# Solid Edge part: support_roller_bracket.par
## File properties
Title: Support roller bracket
Author: Abhinav Rai
Template: Normal.par
Last saved by: Cadcim
Revision: 17
Application: Solid Edge
Material: aluminum
Density: 0 kg/mm^3
Accuracy: 0.99
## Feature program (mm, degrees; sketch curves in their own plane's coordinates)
sketch for "unnamed Protrusion 1" #1 plane through (0, 0, 0) normal (0, -1, 0) x-axis (1, 0, 0)
  circle centre (0, -138.9237) radius 3.81
sketch for "unnamed Protrusion 1" #2 plane through (0, 0, 0) normal (0, -1, 0) x-axis (1, 0, 0)
  line (143.637, -99.9249) -> (-143.637, -99.9249)
  line (-143.637, -99.9249) -> (-143.637, -115.1647)
  line (-143.637, -115.1647) -> (-61.0846, -156.7704)
  line (-61.0846, -156.7704) -> (-61.0846, -162.9363)
  line (-61.0846, -162.9363) -> (61.0846, -162.9363)
  line (61.0846, -156.7704) -> (61.0846, -162.9363)
  line (143.637, -115.1647) -> (61.0846, -156.7704)
  line (143.637, -99.9249) -> (143.637, -115.1647)
  dimension (linear) = 143.637
extrude "unnamed Protrusion 1" add finite 101.6 symmetric
fillet "Round_1" radius 31.75
fillet "Round_2" radius 6.35
sketch for "unnamed Protrusion 2" plane through (0, 0, 67.2512) normal (1, 0, 0) x-axis (0, 1, 0)
  arc centre (-23.4135, -61.792) radius 19.05 from (-23.4135, -42.742) to (-42.405, -60.3002) ccw
  line (-50.8, -167.1761) -> (-42.405, -60.3002)
  line (-50.8, -167.1761) -> (50.8, -167.1761)
  line (45.7777, -60.8928) -> (50.8, -167.1761)
  arc centre (26.749, -61.792) radius 19.05 from (26.749, -42.742) to (45.7777, -60.8928) cw
  line (19.05, -42.742) -> (26.749, -42.742)
  line (19.05, -64.967) -> (19.05, -42.742)
  arc centre (0, -64.967) radius 19.05 from (-19.05, -64.967) to (19.05, -64.967) ccw
  line (-19.05, -42.742) -> (-19.05, -64.967)
  line (-23.4135, -42.742) -> (-19.05, -42.742)
extrude "unnamed Protrusion 2" add to key point symmetric
sketch for "ExtrudedCutout_1" plane through (0, 0, 0) normal (0, -1, 0) x-axis (1, 0, 0)
  line (-128.3193, 24.5092) -> (125.6319, 24.5092)
  line (125.6319, 24.5092) -> (125.6319, -99.9249)
  line (125.6319, -99.9249) -> (-128.3193, -99.9249)
  line (-128.3193, -99.9249) -> (-128.3193, 24.5092)
extrude "ExtrudedCutout_1" cut finite 203.2 symmetric
chamfer "Chamfer_1" setback 5.08
rib "Rib_1"  Thickness = 25.4 mm
mirror "unnamed Mirror 1" of "Rib_1" about plane through (0, 0, 0) normal (1, 0, 0)
rib "unnamed Rib 1"
sketch for "Hole_1" plane through (0.1259, 0, -162.9363) normal (0, 0, -1) x-axis (-1, 0, 0)
  hole centre (0.1259, 0) bore radius 25.4
hole "Hole_1" diameter 50.8 through
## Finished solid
Body 1: solid body, 55 faces, 142 edges, 86 vertices.
  Faces by surface: plane 38, cylinder 17
  Edges by curve: line 106, circle 34, intersection 2
Bounding box of the edges (mm): 379.121 x 101.600 x 187.446, from (-189.5605, -50.8, -162.9363) to (189.5605, 50.8, 24.5092).
Cylindrical faces by radius (mm): R3.81 x2, R6.35 x2, R19.05 x6, R25.4 x1, R31.75 x4, R55.372 x2
Planar faces by outward normal: +x 4, +y 5, +z 5, -x 4, -y 5, -z 1, oblique 14
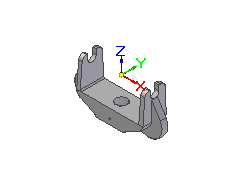
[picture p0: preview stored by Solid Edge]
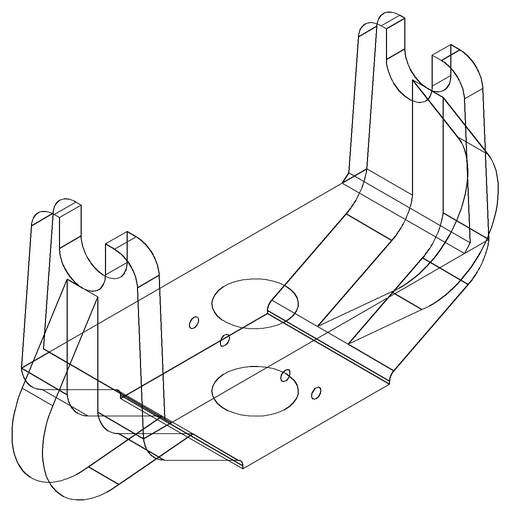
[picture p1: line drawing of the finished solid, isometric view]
